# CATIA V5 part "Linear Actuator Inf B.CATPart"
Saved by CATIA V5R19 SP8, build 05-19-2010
Part number: Linear Actuator Inf B
Bounding box of the stored display mesh (mm): x -19.994 to 19.994, y 110 to 424.822, z 600.006 to 639.994
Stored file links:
  G:\EU_thinkMotion\CFAO_2010\MMS_groupe3\MMS_groupe3\A reprendre\fovide\fovide\Linear Actuator Inf B.CATPart
  G:\EU_thinkMotion\CFAO_2010\MMS_groupe3\MMS_groupe3\A reprendre\fovide\fovide\fovide.CATProduct
  G:\EU_thinkMotion\CFAO_2010\MMS_groupe3\MMS_groupe3\A reprendre\fovide\fovide\Linear Actuator Inf A.CATPart
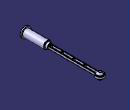
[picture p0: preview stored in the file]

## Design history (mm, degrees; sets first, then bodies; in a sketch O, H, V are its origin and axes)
Set1
  Plane1: linked copy from another document
  Line1: linked copy from another document
  DatumCurve1: linked copy from another document
  Plane2: linked copy from another document
  Point1 "Point.N": linked copy from another document
  Line2: linked copy from another document
Body1 (main body)
  Sketch1 on Plane1, origin (0, 0, 0), H (0, 1, 0), V (0, 0, 1)
    line L1 (110, 640) -> (110, 620)
    line L2 (110, 620) -> (210, 620)
    line L3 (210, 620) -> (210, 630)
    line L4 (210, 630) -> (200, 630)
    line L5 (200, 630) -> (200, 635)
    line L6 (200, 635) -> (115, 635)
    line L7 (115, 635) -> (115, 640)
    line L8 (115, 640) -> (110, 640)
    reference projected line E1 (410, 620) -> (10, 620) from Line1
    reference projected line E2 (115, 605) -> (115, 635) from edge of DatumCurve1
    length L2 = 100
    length L1 = 20
    length L8 = 5
    length L7 = 5
    length L4 = 10
    length L3 = 10
    vertical: L1 V, L3 V, L5 V, L7 V
    horizontal: L2 H, L4 H, L6 H, L8 H
    coincidence: L2 E1, L7 E2
  Shaft1: profile Sketch1, axis Line1, angle 360
  Sketch2 on Plane2, origin (0, 0, 620), H (1, 0, 0), V (0, 1, 0)
    arc A1 centre (0, 410) radius 15 from (-7.5, 397.0096) to (7.5, 397.0096) cw
    point P1 (0, 410)
    reference projected point E1 (0, 410) from Point1
    line L1 (7.5, 397.0096) -> (7.5, 210)
    line L2 (7.5, 210) -> (-7.5, 210)
    line L3 (-7.5, 210) -> (-7.5, 397.0096)
    reference projected line E2 (0, 410) -> (0, 10) from Line1
    reference projected line E3 (10, 210) -> (-10, 210) from edge [face of Shaft1 from Sketch1.L3 | face of Shaft1 from Sketch1.L4]
    radius A1 = 15
    distance L3 L1 = 15
    distance L1 E2 = 7.5
    coincidence: P1 E1, E3 L2
    vertical: L1 V, L3 V
    horizontal: L2 H
  Pad1: profile Sketch2, direction (0, 0, 1), length 5, mirrored extent
  Sketch3 on end face of Pad1, origin (0, 0, 625), H (1, 0, 0), V (0, 1, 0)
    line L1 (-5, 255) -> (5, 255)
    line L2 (5, 255) -> (5, 215)
    line L3 (5, 215) -> (-5, 215)
    line L4 (-5, 215) -> (-5, 255)
    reference projected line E1 (10, 210) -> (-10, 210) from edge [face of Shaft1 from Sketch1.L3 | face of Shaft1 from Sketch1.L4]
    reference projected line E2 (0, 410) -> (0, 10) from Line1
    point P5 (-5, 260)
    line L5 (-5, 260) -> (5, 260)
    line L6 (5, 260) -> (5, 300)
    line L7 (5, 300) -> (-5, 300)
    line L8 (-5, 300) -> (-5, 260)
    point P7 (5, 300)
    point P9 (-5, 305)
    line L9 (-5, 305) -> (5, 305)
    line L10 (5, 305) -> (5, 345)
    line L11 (5, 345) -> (-5, 345)
    line L12 (-5, 345) -> (-5, 305)
    point P11 (5, 345)
    point P13 (-5, 350)
    line L13 (-5, 350) -> (5, 350)
    line L14 (5, 350) -> (5, 390)
    line L15 (5, 390) -> (-5, 390)
    line L16 (-5, 390) -> (-5, 350)
    point P15 (5, 390)
    distance L3 E1 = 5
    length L2 = 40
    length L1 = 10
    distance L2 E2 = 5
    length L6 = 40
    distance L5 L1 = 5
    length L10 = 40
    distance L7 L9 = 5
    length L14 = 40
    distance L13 L11 = 5
    horizontal: L1 H, L3 H, L5 H, L7 H, L9 H, L11 H, L13 H, L15 H
    vertical: L2 V, L4 V, L6 V, L8 V, L10 V, L12 V, L14 V, L16 V
    coincidence: P5 L4, P7 L2, P9 L4, P11 L2, P13 L4, P15 L2
  Pocket1: profile Sketch3, direction (0, 0, -1), through (limit type 3)
  Sketch4 on Plane1, origin (0, 0, 0), H (0, 1, 0), V (0, 0, 1)
    line L1 (410, 633) -> (410, 625)
    line L2 (410, 625) -> (422, 625)
    point P3 (422, 625)
    line L3 (410, 633) -> (416, 633)
    point P4 (416, 633)
    arc A1 centre (406.8411, 619.8808) radius 16 from (422, 625) to (416, 633) ccw
    point P6 (422, 625)
    point P7 (416, 633)
    reference projected line E1 (410, 570) -> (410, 670) from Line2
    reference projected line E2 (397.0096, 625) -> (425, 625) from edge [face of Pad1 from Sketch2.A1 | end face of Pad1]
    point P8 (416, 607)
    line L4 (416, 607) -> (410, 607)
    point P9 (410, 607)
    line L5 (410, 607) -> (410, 615)
    line L6 (410, 615) -> (422, 615)
    point P11 (422, 615)
    arc A2 centre (406.8411, 620.1192) radius 16 from (416, 607) to (422, 615) ccw
    point P13 (416, 607)
    point P14 (422, 615)
    reference projected line E3 (397.0096, 615) -> (425, 615) from edge [start face of Pad1 | face of Pad1 from Sketch2.A1]
    length L3 = 6
    length L2 = 12
    length L1 = 8
    length L4 = 6
    length L6 = 12
    radius A1 = 16
    radius A2 = 16
    distance L4 L6 = 8
    vertical: L1 V, L5 V
    horizontal: L2 H, L3 H, L4 H, L6 H
    coincidence: P7 P4, P6 P3, L1 E1, L2 E2, P9 L1, P14 P11, P13 P8, L6 E3
  Shaft2: profile Sketch4, axis Line2, angle 360
  Fillet1: radius 1, on end face of Pad1; start face of Pad1; edge [face of Shaft1 from Sketch1.L3 | face of Shaft1 from Sketch1.L4]; edge [face of Shaft1 from Sketch1.L5 | face of Shaft1 from Sketch1.L6]
  Sketch5 on face of Shaft2 from Sketch4.L3, origin (0, 410, 633), H (1, 0, 0), V (0, 1, 0)
    point P1 (0, 0)
    intersected point E1 (0, 0) from Line2
    coincidence: E1 P1
  Hole1: placed by Sketch5, at (0, 410, 633) direction (0, 0, -1), diameter 10, through (limit type 3)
